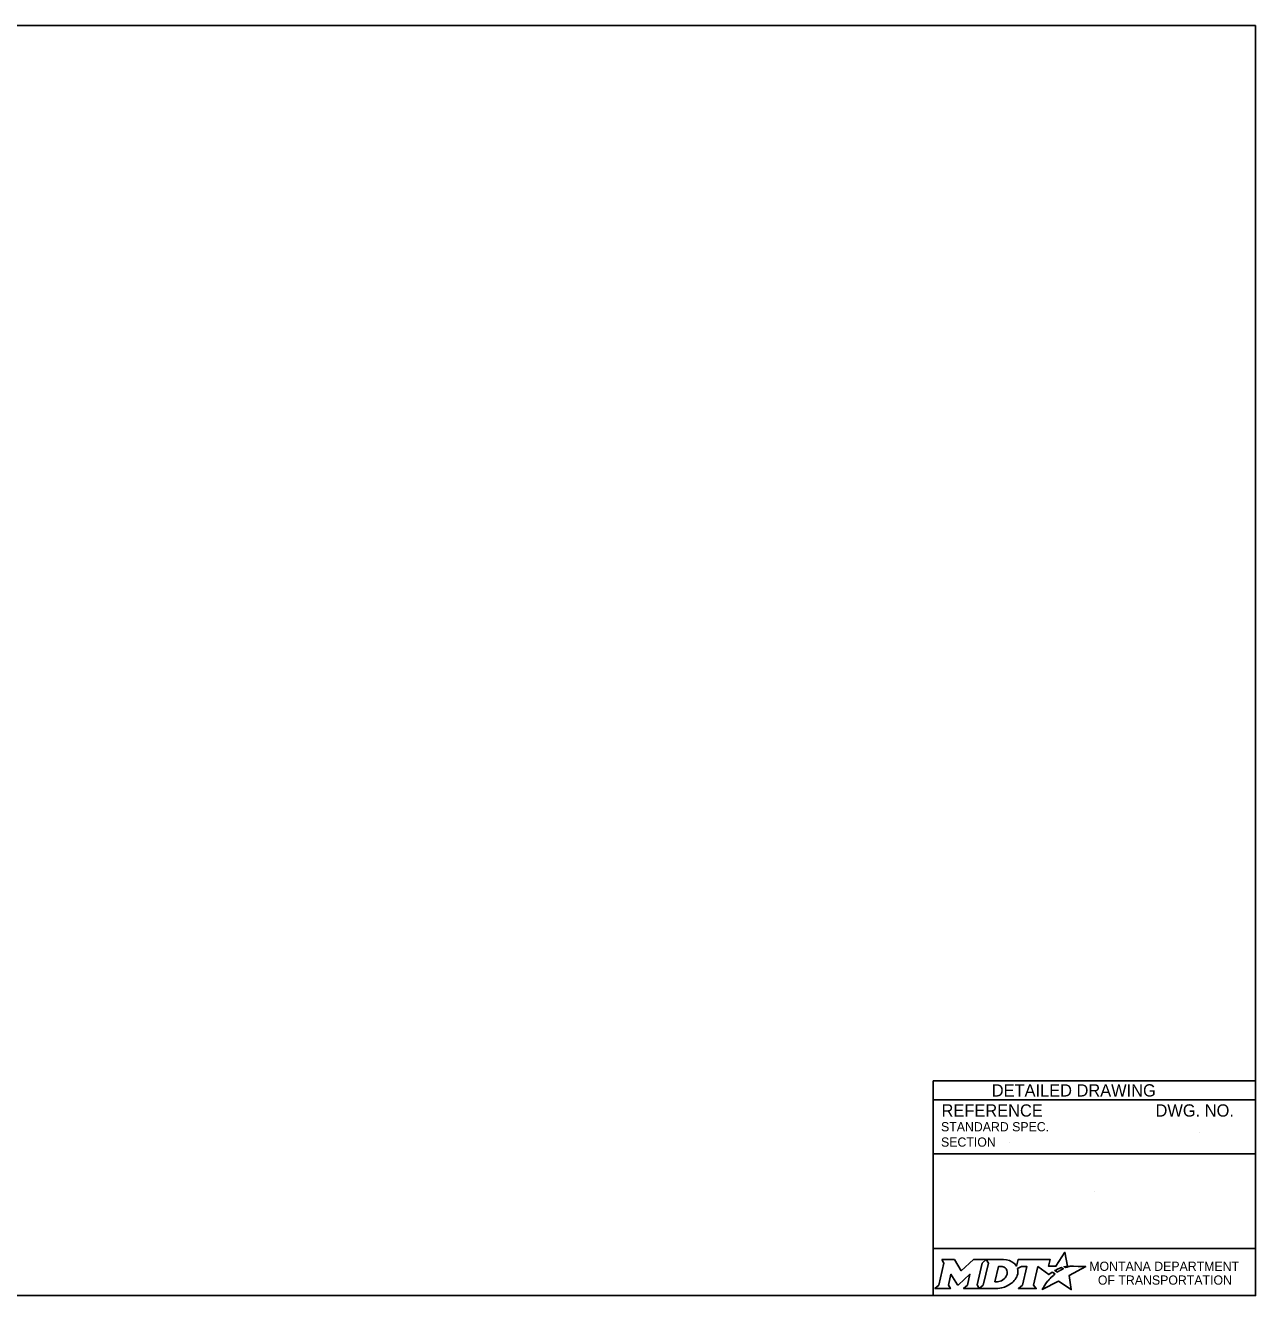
# Model space of a CAD drawing. Extents: x 49940 to 50043, y 49986 to 50011.
# Drawn here: x 50012.92 to 50020.94, y 49999.89 to 50008.16 of the extents above; entities that cross this region are included whole.
import ezdxf

# ---------------------------------------------------------------- set-up
doc = ezdxf.new("R2010")
doc.units = 0
for name, color, linetype in [('Default', 7, 'Continuous'), ('Level 1', 7, 'Continuous'), ('Level 4', 7, 'Continuous')]:
    doc.layers.add(name, color=color, linetype=linetype)

msp = doc.modelspace()

# ---------------------------------------------------------------- linework, layer by layer
at = {"layer": 'Default'}
for points in [[(50018.8933, 50000.1206), (50018.9074, 50000.0972), (50018.8739, 49999.9539), (50018.8482, 49999.9314), (50018.9498, 49999.9314), (50018.9363, 49999.9542), (50018.9525, 50000.0243), (50018.9962, 49999.9553), (50019.0015, 49999.9553), (50019.0766, 50000.0248), (50019.0602, 49999.9537), (50019.0355, 49999.9317), (50019.1371, 49999.9317), (50019.1233, 49999.955), (50019.1565, 50000.0974)], [(50019.1565, 50000.0974), (50019.1818, 50000.1206), (50019.0994, 50000.1206), (50019.0198, 50000.0476), (50018.9753, 50000.1203), (50018.8933, 50000.1206)], [(50019.2954, 50000.1206), (50019.1818, 50000.1206), (50019.1965, 50000.0977), (50019.1626, 49999.9539), (50019.1371, 49999.9317), (50019.2477, 49999.9317)], [(50019.7003, 50000.0679), (50019.69, 50000.0735), (50019.7016, 50000.0763), (50019.7132, 50000.0783), (50019.6958, 50000.1684), (50019.6363, 50000.0771), (50019.589, 50000.0764), (50019.5993, 50000.1205), (50019.3901, 50000.1206), (50019.38, 50000.0781), (50019.3742, 50000.0864)], [(50019.3194, 50000.0339), (50019.3182, 50000.0258), (50019.315, 50000.0165), (50019.3108, 50000.0083), (50019.3052, 50000.0008), (50019.2987, 49999.9939), (50019.2908, 49999.9876), (50019.2825, 49999.9829), (50019.2734, 49999.979), (50019.2643, 49999.9767), (50019.2551, 49999.9758), (50019.2392, 49999.9758), (50019.2628, 50000.0758), (50019.2788, 50000.0758), (50019.2864, 50000.0752), (50019.294, 50000.0733), (50019.3006, 50000.0703), (50019.3067, 50000.0661), (50019.3115, 50000.0611), (50019.3152, 50000.0551), (50019.3179, 50000.0489), (50019.3195, 50000.0415), (50019.3195, 50000.0385), (50019.3194, 50000.0339)], [(50019.3868, 50000.0615), (50019.4114, 50000.0746), (50019.4483, 50000.0746), (50019.4197, 49999.9541), (50019.3922, 49999.9314), (50019.5084, 49999.9314), (50019.4914, 49999.9543), (50019.5196, 50000.0745), (50019.5909, 50000.0228), (50019.612, 50000.0379), (50019.6317, 50000.027)], [(50019.5759, 49999.9711), (50019.5606, 49999.9467), (50019.5559, 49999.9392), (50019.5501, 49999.9306), (50019.5478, 49999.9263), (50019.6531, 49999.9794), (50019.737, 49999.9243), (50019.7239, 50000.017), (50019.8308, 50000.0754), (50019.7815, 50000.0762), (50019.7514, 50000.0766), (50019.7306, 50000.0769), (50019.7238, 50000.0754), (50019.7189, 50000.0742), (50019.7105, 50000.0719), (50019.7003, 50000.0679)], [(50019.6499, 50000.0403), (50019.6475, 50000.0386), (50019.6292, 50000.0482), (50019.6395, 50000.0539), (50019.6436, 50000.0561), (50019.6522, 50000.0601), (50019.6579, 50000.0627), (50019.6658, 50000.0657), (50019.6731, 50000.0684), (50019.6849, 50000.061), (50019.6809, 50000.0589), (50019.6763, 50000.0564), (50019.6721, 50000.0542), (50019.6671, 50000.0513), (50019.6652, 50000.0502), (50019.6625, 50000.0486), (50019.66, 50000.0472), (50019.6577, 50000.0456), (50019.6551, 50000.0438), (50019.6524, 50000.042), (50019.6499, 50000.0403)], [(50019.2934, 49999.939), (50019.3018, 49999.9416), (50019.3148, 49999.947), (50019.3352, 49999.958)], [(50019.5898, 49999.9872), (50019.5898, 49999.9872)]]:
    msp.add_lwpolyline(points, dxfattribs=at)
for centre, radius, start, end in [((50019.3185, 50000.0422), 0.0709, 339.53292, 15.85821), ((50019.2745, 50000.0595), 0.1183, 300.91025, 339.13831)]:
    msp.add_arc(centre, radius, start, end, dxfattribs=at)
for centre, major_axis, ratio, start_param, end_param in [((50019.2933, 50000.0732), (0.0834, -0.0037), 0.568097, 0.61298, 1.570796), ((50019.3489, 50000.0805), (0.0361, -0.0295), 0.469099, 1.225588, 1.570796), ((50019.6206, 50000.0173), (-0.0112, -0.0097), 0.021651, 3.157348, 6.283185), ((50019.5829, 49999.9791), (-0.00694, -0.00806), 0.008222, 0, 3.137361), ((50019.5996, 49999.9974), (-0.0098, -0.0102), 0.016458, 3.141593, 6.279097), ((50019.248, 50000.08), (0, 0.1484), 0.987302, 3.139398, 3.456847)]:
    msp.add_ellipse(centre, major_axis=major_axis, ratio=ratio, start_param=start_param, end_param=end_param, dxfattribs=at)
at = {"layer": 'Level 1'}
msp.add_lwpolyline([(50020.9378, 50008.1646), (50009.7374, 50008.1646), (50009.7374, 49999.8856), (50020.9378, 49999.8856)], close=True, dxfattribs=at)
at = {"layer": 'Level 4'}
for p, q in [((50020.9378, 50001.2856), (50018.8378, 50001.2856)), ((50018.8378, 50001.2856), (50018.8378, 49999.8856)), ((50020.9378, 50001.1606), (50018.8378, 50001.1606)), ((50020.5739, 50000.9455), (50020.5739, 50000.9455)), ((50019.3321, 50000.8861), (50019.3321, 50000.8861)), ((50020.9378, 50000.8106), (50018.8378, 50000.8106)), ((50019.8878, 50000.5615), (50019.8878, 50000.5615)), ((50020.9378, 50000.1925), (50018.8378, 50000.1925))]:
    msp.add_line(p, q, dxfattribs=at)

# ---------------------------------------------------------------- texts
at = {"layer": 'Default'}
for s, p in [('MONTANA DEPARTMENT', (50019.854, 50000.0468)), ('OF TRANSPORTATION', (50019.9102, 49999.9568))]:
    msp.add_text(s, height=0.06, dxfattribs=at).set_placement(p)
at = {"layer": 'Level 4'}
for s, height, p in [('DETAILED DRAWING', 0.0799, (50019.2188, 50001.1831)), ('REFERENCE', 0.08, (50018.8914, 50001.0522)), ('DWG. NO.', 0.08, (50020.2856, 50001.0522)), ('STANDARD SPEC.', 0.06, (50018.8881, 50000.9562)), ('SECTION', 0.06, (50018.8881, 50000.8562))]:
    msp.add_text(s, height=height, dxfattribs=at).set_placement(p)

doc.saveas('drawing.dxf')
